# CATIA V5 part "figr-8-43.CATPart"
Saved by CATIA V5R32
Part number: Part1
Bounding box of the stored display mesh (mm): x -50 to 50, y -50 to 50, z 0 to 25
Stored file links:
  D:\PROJECTS\Project 2022\CATIA V5 6R 2022\Resources\Part Files\c08_catia_v5_6r2022_prt\figr-8-43.CATPart
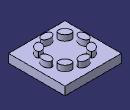
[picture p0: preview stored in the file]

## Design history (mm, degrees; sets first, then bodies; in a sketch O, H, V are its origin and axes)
Body1 (main body)
  Sketch1 on xy-plane, origin (0, 0, 0), H (1, 0, 0), V (0, 1, 0)
    line L1 (-50, 50) -> (50, 50)
    line L2 (50, 50) -> (50, -50)
    line L3 (50, -50) -> (-50, -50)
    line L4 (-50, -50) -> (-50, 50)
    axis line L5 (50, -50) -> (-50, 50)
    length L2 = 100
    length L3 = 100
    horizontal: L1 H, L3 H
    vertical: L2 V, L4 V
    midpoint: L5 O
  Pad1: profile Sketch1, direction (0, 0, 1), length 15
  Sketch2 on face of Pad1, origin (0, 0, 15), H (1, 0, 0), V (0, 1, 0)
    point P1 (0, -32.9864)
    ellipse A1 centre (0, -32.9864) semi-axes 9.9006, 6.5465 rotation 0
    point P2 (0, -26.4399)
    coincidence: P1 V, P2 V, A1 P2
  Pad2: profile Sketch2, direction (0, 0, 1), length 10
  CircPattern1: of Pad2, instances 8, angular step 45 {= 360.0*1 deg/CircPattern1.AngularNumber}, axis from edge of Sketch3
  Sketch3 on yz-plane, origin (0, 0, 0), H (0, 1, 0), V (0, 0, 1)
    line L1 (0, 0) -> (0, 18.4864)
    vertical: L1 V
